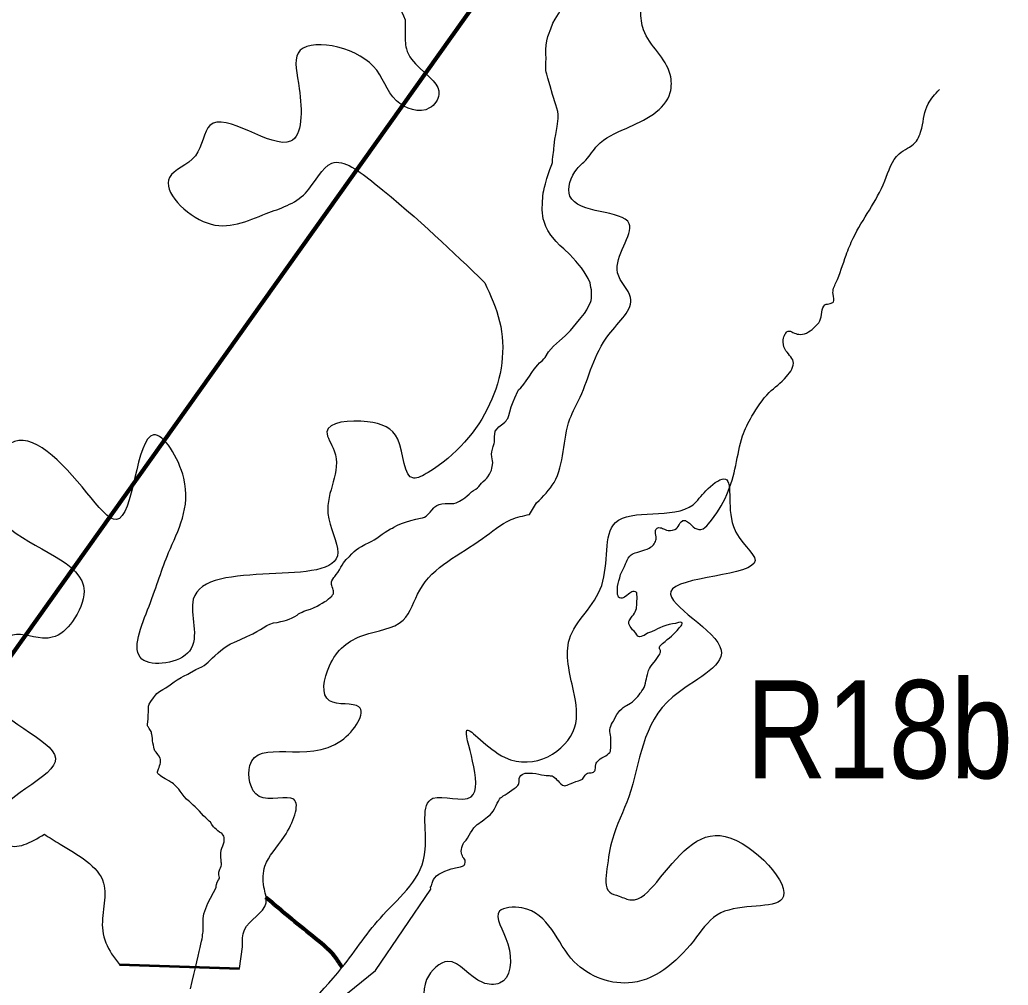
# Model space of a CAD drawing. Extents: x 553962 to 842807, y 8883888 to 9032388.
# Drawn here: x 709342 to 714375, y 8962615 to 8967533 of the extents above; entities that cross this region are included whole.
import ezdxf
from ezdxf.enums import TextEntityAlignment as Align

# ---------------------------------------------------------------- set-up
doc = ezdxf.new("R2010")
doc.units = 0
doc.header["$LTSCALE"] = 200
for name, color, linetype, lineweight in [('24', 7, 'Continuous', 25), ('50', 7, 'Continuous', 80), ('51', 7, 'Continuous', 25), ('9', 7, 'Continuous', 90)]:
    doc.layers.add(name, color=color, linetype=linetype, lineweight=lineweight)
doc.layers.add('53', color=7, linetype='Continuous')

msp = doc.modelspace()

# ---------------------------------------------------------------- linework, layer by layer
at = {"layer": '24'}
for points in [[(712046.7, 8967486.3), (712056.6, 8967515.1), (712068, 8967536.8), (712085.3, 8967563.8), (712094.3, 8967578.9), (712108.4, 8967604.9), (712114.9, 8967617.8), (712124.7, 8967632.2), (712136.2, 8967644.8), (712162, 8967671.2), (712191.7, 8967711.2)], [(712010.1, 8966662.7), (712013.6, 8966680.7), (712018.3, 8966697.9), (712026.1, 8966724.5), (712034.9, 8966749.9), (712041.8, 8966770), (712048.3, 8966786.7), (712051.1, 8966796), (712053.9, 8966805.4), (712055.1, 8966820.5), (712056.4, 8966835.5), (712060.8, 8966868), (712061.7, 8966875.3), (712063.1, 8966891.8), (712067.3, 8966924.5), (712071.5, 8966948.2), (712079.1, 8966989.8), (712083.9, 8967030.2), (712084.2, 8967050), (712082.3, 8967065.3), (712071.5, 8967099), (712054.8, 8967152.1), (712043.2, 8967196.6), (712031.2, 8967236.3), (712025.9, 8967255.3), (712022.9, 8967266.6), (712021.3, 8967275.1), (712020.1, 8967289.9), (712021.3, 8967318.5), (712021.8, 8967333), (712019.9, 8967363), (712020.8, 8967382), (712022.9, 8967404.1), (712025.7, 8967426.3), (712030.2, 8967447.9), (712034.5, 8967455.4), (712046.7, 8967486.3)], [(711759.8, 8965408.9), (711762.8, 8965437.7), (711772.3, 8965449.9), (711782, 8965460.1), (711801.8, 8965475.1), (711812, 8965483.4), (711818.1, 8965490.2), (711822.9, 8965496.2), (711826.4, 8965502.4), (711831.9, 8965516.8), (711836.6, 8965535), (711844.2, 8965561.3), (711853.7, 8965587.6), (711862.3, 8965606.9), (711878.9, 8965640.7), (711881.7, 8965647.3), (711893.7, 8965658.9), (711907.8, 8965676), (711921, 8965693.7), (711937.6, 8965716.8), (711948.9, 8965735.5), (711961.2, 8965752.8), (711979.2, 8965774.9), (711988.2, 8965784.6), (712003.5, 8965798), (712011.1, 8965805.6), (712017.1, 8965812.5), (712033.5, 8965840.7), (712059.2, 8965870.5), (712089.4, 8965897), (712119.3, 8965922.3), (712146.4, 8965950.7), (712192.1, 8966005.7), (712217.5, 8966036.2), (712228.7, 8966055.3), (712241.9, 8966080.2), (712247.9, 8966092.2), (712251.6, 8966102.6), (712253.4, 8966114.4), (712253.2, 8966120.2), (712253.4, 8966136.1), (712252.7, 8966157.1), (712250.2, 8966169.6), (712246, 8966192.4), (712235.8, 8966214.5), (712215.5, 8966249.6), (712202.1, 8966269.7), (712191.2, 8966283.1), (712173.9, 8966303.2), (712143.5, 8966337.1), (712111.7, 8966366.2), (712091.6, 8966383.7), (712072.8, 8966403.6), (712045.8, 8966436.3), (712030.5, 8966459.8), (712020.8, 8966479.7), (712012.2, 8966506.2), (712007.8, 8966519.2), (712005.3, 8966533.7), (712003.9, 8966547.6), (712002.7, 8966566.2), (712003.7, 8966600.8), (712005.5, 8966632), (712006.5, 8966651.9), (712010.1, 8966662.7)], [(711099.7, 8964859.2), (711120.7, 8964869.8), (711134.7, 8964876.2), (711147.4, 8964883.5), (711161, 8964892.7), (711174.5, 8964903), (711187.8, 8964912.1), (711202.9, 8964922.2), (711217, 8964931.3), (711230.3, 8964939.3), (711239.5, 8964943.7), (711247.4, 8964948.7), (711265.6, 8964957.7), (711286, 8964966.3), (711305.5, 8964973.4), (711334.1, 8964982.8), (711358.9, 8964988.4), (711381.9, 8964993.7), (711392.8, 8964996.2), (711403.7, 8965000), (711411.9, 8965003.8), (711419, 8965010.9), (711432, 8965024.8), (711439.7, 8965034.5), (711450.9, 8965046), (711456.2, 8965052.5), (711466, 8965058.7), (711477.8, 8965064.3), (711491.9, 8965066.9), (711508.5, 8965068.4), (711519.7, 8965068.4), (711532, 8965068.8), (711539, 8965068.8), (711545.8, 8965068.8), (711552.3, 8965069.7), (711564.4, 8965073), (711580.7, 8965080), (711598.1, 8965090.7), (711608.4, 8965097.7), (711619.6, 8965107.5), (711630.5, 8965116.6), (711636.6, 8965123.5), (711642.2, 8965128), (711652.5, 8965134.4), (711664.9, 8965142.4), (711673.5, 8965148.9), (711679.4, 8965154.8), (711686.5, 8965163.6), (711692.4, 8965171.9), (711702.1, 8965181.3), (711711.6, 8965189), (711715.2, 8965192.5), (711719.9, 8965197.2), (711725.5, 8965204.8), (711734.4, 8965219), (711739.7, 8965228.7), (711743.5, 8965239), (711746.5, 8965248.2), (711748.2, 8965257.3), (711748.8, 8965265), (711750.3, 8965277.4), (711749.5, 8965286.2), (711747.7, 8965295.9), (711745, 8965307.4), (711743.6, 8965319.8), (711745.3, 8965332.2), (711748.9, 8965344.8), (711753.3, 8965359.9), (711757.7, 8965374.3), (711758.6, 8965382), (711758.9, 8965390.2), (711759.8, 8965401.7), (711759.8, 8965408.9)], [(712421.5, 8964748.8), (712426.5, 8964761.1), (712431.3, 8964771.9), (712434.6, 8964780.6), (712440.2, 8964790.3), (712447.7, 8964800.3), (712455, 8964807.6), (712460, 8964811.5), (712466.4, 8964814.6), (712475.8, 8964817), (712489.2, 8964821.2), (712503.7, 8964825.6), (712514.6, 8964829.5), (712524.9, 8964832.9), (712536.6, 8964836.8), (712547.2, 8964841.8), (712554.2, 8964846), (712560.1, 8964850.4), (712564, 8964853.5), (712568.7, 8964858.5), (712572.9, 8964864.1), (712575.7, 8964869.4), (712578.2, 8964875.8), (712581, 8964882.2), (712582.1, 8964887.8), (712582.1, 8964894.2), (712581.8, 8964899.4), (712580.7, 8964907.5), (712579.6, 8964916.1), (712579, 8964925.6), (712579, 8964931.7), (712580.2, 8964935.9), (712583.5, 8964940.6), (712587.1, 8964943.4), (712590.5, 8964945.7), (712596.1, 8964946.2), (712603.6, 8964945.7), (712610, 8964944.3), (712614.8, 8964942.3), (712619.8, 8964939.8), (712624.8, 8964937.3), (712628.9, 8964935.6), (712634.8, 8964933.4), (712643.5, 8964931.5), (712654.6, 8964931.5), (712665.8, 8964933.1), (712678, 8964937), (712685.3, 8964940.7), (712689.2, 8964944.3), (712694.8, 8964952.1), (712700.1, 8964960.4), (712705.4, 8964969.6), (712709.6, 8964975.5), (712715.7, 8964980), (712719, 8964982.2), (712724.1, 8964983), (712728.5, 8964983), (712732.4, 8964981.6), (712735.5, 8964979.4), (712742.2, 8964975.2), (712751.4, 8964968.5), (712759.2, 8964961.6), (712771.2, 8964950.7), (712778.7, 8964943.7), (712788.8, 8964939.7)], [(710000.6, 8963922), (709997.1, 8963929.1), (709994.4, 8963933.2), (709992.9, 8963937.1), (709992.3, 8963944.1), (709993.5, 8963956.8), (709995.3, 8963972.7), (709995.9, 8963988.3), (709997, 8964009.5), (709997, 8964025.7), (709997.6, 8964037.2), (710000.6, 8964046.7), (710009.7, 8964060.8), (710023.7, 8964079.6), (710032.8, 8964091.9), (710040.8, 8964100.5), (710053.5, 8964110.8), (710070.6, 8964121.1), (710085.3, 8964130), (710108.5, 8964144.7), (710128.6, 8964161.2), (710143.6, 8964170.3), (710163.7, 8964183.3), (710175.5, 8964189.5), (710198.5, 8964199.8), (710207.1, 8964204.8), (710239.1, 8964222.6), (710269, 8964236.8), (710280.8, 8964244.5), (710300.8, 8964260.7), (710318.8, 8964277.8), (710324.1, 8964282.8), (710334.9, 8964292.4), (710352.3, 8964308), (710365.6, 8964319.5), (710381.8, 8964332.8), (710398.6, 8964344), (710415.8, 8964353.7), (710432, 8964361.1), (710465.5, 8964376), (710498.9, 8964391), (710528.1, 8964404.3), (710549.6, 8964416.4), (710567.2, 8964426.9), (710581.1, 8964436), (710600.6, 8964447), (710615.1, 8964454.3), (710633.7, 8964461.1), (710652, 8964463.5), (710671.7, 8964467.6), (710688.3, 8964470.8), (710699.5, 8964474.7), (710713.8, 8964479.8), (710728.9, 8964486.9), (710742.8, 8964493.1), (710755.2, 8964500.7), (710762.2, 8964506.3), (710768.7, 8964511), (710780, 8964516), (710789.1, 8964519.9), (710804.5, 8964525.5), (710822.7, 8964530.8), (710837.2, 8964537.9), (710856, 8964546), (710870.1, 8964554), (710881.6, 8964561.9), (710894.9, 8964569.9), (710903.8, 8964573.7), (710914.7, 8964583.2), (710923, 8964589.9), (710931.2, 8964597.6), (710935.3, 8964602.9), (710939.2, 8964609.1), (710940.1, 8964615.3), (710940.2, 8964623.8), (710938.7, 8964629.9), (710936.9, 8964636.7), (710933.1, 8964645), (710930.7, 8964651.2), (710929.2, 8964656.8), (710928.9, 8964662.4), (710929.8, 8964669.2), (710931.9, 8964675.1), (710935.4, 8964682.7), (710941.9, 8964691.8), (710946.3, 8964697.5), (710953.8, 8964707.1), (710960.9, 8964717.7), (710970, 8964730.7), (710977.7, 8964744), (710983.9, 8964754.9), (710990.4, 8964766.4), (710997.2, 8964774.6), (711004.6, 8964783.2), (711020.6, 8964799.3), (711033.6, 8964812.3), (711045.1, 8964823.8), (711055.7, 8964832.3), (711067.5, 8964840.6), (711082.3, 8964849.4), (711099.7, 8964859.2)], [(712479.6, 8964525.8), (712481.6, 8964533.3), (712482.7, 8964541.1), (712483.2, 8964550.3), (712483.8, 8964560.5), (712484.4, 8964573.6), (712485, 8964582.2), (712485, 8964591.4), (712483.8, 8964606.2), (712483.8, 8964613.4), (712481.3, 8964617.1), (712476.6, 8964619.3), (712470.7, 8964620.7), (712463.8, 8964620.1), (712458.8, 8964618.2), (712448.8, 8964612.1), (712441, 8964607), (712432.3, 8964600.3), (712421.7, 8964591.7), (712415, 8964587.8), (712409.2, 8964587.2), (712402.8, 8964586.4), (712395.8, 8964588.6), (712390.5, 8964592.3), (712388.2, 8964598.1), (712386, 8964605.4), (712385.2, 8964611.2), (712385.5, 8964621.5), (712384.9, 8964634), (712386.1, 8964646), (712388.3, 8964661.9), (712392.7, 8964675.6), (712396.7, 8964690.6), (712401.4, 8964706.8), (712407.8, 8964721.5), (712415.9, 8964737.1), (712421.5, 8964748.8)], [(712600.3, 8964302.1), (712603.4, 8964308), (712604.8, 8964311.1), (712605.3, 8964314.4), (712604.8, 8964319.7), (712603.1, 8964323), (712600.9, 8964325.8), (712599.2, 8964330.3), (712598.7, 8964334.2), (712599.8, 8964337.5), (712601.4, 8964341.7), (712604.8, 8964346.2), (712609.8, 8964350.6), (712615.1, 8964355.3), (712628.8, 8964366.5), (712638.3, 8964375.4), (712650.5, 8964385.2), (712660.2, 8964393.8), (712668.8, 8964401), (712677.8, 8964410), (712689.8, 8964422.2), (712696.5, 8964430.3), (712701.5, 8964436.7), (712709.8, 8964445.6), (712713.5, 8964450.3), (712715.4, 8964457), (712715.4, 8964460.9), (712711.8, 8964463.2), (712705.1, 8964464), (712695.6, 8964462.3), (712680.3, 8964458.4), (712665.5, 8964456.2), (712648, 8964452.2), (712631.8, 8964446.9), (712615.9, 8964442.5), (712600.6, 8964435.8), (712589.1, 8964429.9), (712577.4, 8964424.3), (712558.7, 8964416), (712538.9, 8964407.9), (712520.6, 8964397.3), (712515, 8964394), (712505.5, 8964390.7), (712498, 8964389.8), (712492.4, 8964391.2), (712489.6, 8964393.4), (712484, 8964400.1), (712478.7, 8964408.2), (712470.1, 8964417.7), (712462, 8964426), (712455.8, 8964435.5), (712450.5, 8964442.2), (712446.1, 8964449.4), (712443.3, 8964455.6), (712443.3, 8964460.6), (712443.3, 8964465.3), (712443.9, 8964467.8), (712445.3, 8964471.7), (712448.9, 8964477), (712453.4, 8964484), (712460.3, 8964494.3), (712466.2, 8964501), (712472.6, 8964510.7), (712476.2, 8964517.7), (712479.6, 8964525.8)], [(712364.7, 8963959.7), (712369, 8963967.4), (712374, 8963979.4), (712382.1, 8963994.2), (712391.6, 8964008.1), (712397.2, 8964015.1), (712407.2, 8964023.7), (712414.7, 8964029.3), (712425.1, 8964036.3), (712431.6, 8964040.4), (712451.1, 8964051.2), (712462, 8964058.8), (712470.7, 8964066.8), (712480.2, 8964076.6), (712488.5, 8964085), (712495.5, 8964093.9), (712501.6, 8964102.5), (712505.9, 8964108.6), (712510.1, 8964115), (712516.8, 8964123.3), (712521.6, 8964132.2), (712524.6, 8964141.4), (712527.7, 8964153.4), (712529.9, 8964164.8), (712532.7, 8964175.4), (712535.5, 8964185.8), (712537.5, 8964198.3), (712541.4, 8964211.4), (712543.9, 8964218.9), (712548.1, 8964228.1), (712554.2, 8964237), (712562.9, 8964248.1), (712571.5, 8964260.7), (712579.4, 8964269), (712590, 8964284.1), (712596.7, 8964295.4), (712600.3, 8964302.1)], [(712058, 8963677.9), (712064.5, 8963673.2), (712070.9, 8963667.3), (712075.7, 8963662.8), (712082.7, 8963655.8), (712088.8, 8963649.4), (712097.8, 8963640.5), (712105.9, 8963634.6), (712111.7, 8963631.8), (712117.6, 8963631.5), (712122.6, 8963632.4), (712129.6, 8963634.1), (712136, 8963636.8), (712144.1, 8963640.2), (712158.2, 8963646.8), (712172.7, 8963652.3), (712186.9, 8963656.2), (712195.8, 8963659.8), (712206.7, 8963664.9), (712211.5, 8963669.6), (712214.5, 8963674.6), (712220.7, 8963684.6), (712224.3, 8963689.1), (712227.7, 8963692.2), (712232.4, 8963695.2), (712239.1, 8963696.6), (712244.4, 8963697.5), (712251.4, 8963697.7), (712258.6, 8963698.3), (712263.1, 8963700), (712266.7, 8963703.3), (712269.8, 8963706.4), (712271.2, 8963710.3), (712272, 8963714.7), (712272.9, 8963720.2), (712273.7, 8963729.4), (712275.1, 8963740.3), (712277.1, 8963746.2), (712279.9, 8963750.6), (712282.9, 8963754.2), (712290.2, 8963761.2), (712297.4, 8963767.6), (712305.2, 8963772.9), (712316.1, 8963778.5), (712326.2, 8963784.3), (712333.8, 8963789.8), (712340.5, 8963795.4), (712346.3, 8963800.7), (712349.4, 8963807.4), (712350.5, 8963814.6), (712351.3, 8963823), (712351.6, 8963830.8), (712351.9, 8963841.9), (712351.9, 8963855.3), (712351.9, 8963871.4), (712352.2, 8963880.8), (712350.5, 8963887.5), (712348, 8963898.4), (712346.6, 8963905.9), (712346.6, 8963916), (712348, 8963926.3), (712351.1, 8963935.2), (712355.8, 8963944.4), (712360.8, 8963953.3), (712364.7, 8963959.7)], [(710341.7, 8963112), (710341.4, 8963118.8), (710343.5, 8963128.8), (710347.6, 8963139.4), (710354.1, 8963151.2), (710357.1, 8963156.2), (710358.5, 8963160.6), (710358.8, 8963163.6), (710357.9, 8963170.6), (710356.5, 8963178), (710355.6, 8963184.5), (710356.2, 8963190.1), (710358, 8963196.8), (710361.5, 8963206.8), (710364.5, 8963213.6), (710368.3, 8963221.3), (710369.5, 8963228.1), (710368.6, 8963236.9), (710367.1, 8963241.9), (710366.8, 8963249.6), (710365.6, 8963268.8), (710365.6, 8963287.6), (710367.7, 8963303.5), (710370.7, 8963313.2), (710376.6, 8963324.4), (710380.1, 8963334.5), (710382.8, 8963345.1), (710383.7, 8963357.7), (710383.1, 8963367.8), (710381.6, 8963373.7), (710378.1, 8963379.6), (710373, 8963385.8), (710370.3, 8963388.6), (710365.3, 8963391.5), (710358.8, 8963395.4), (710350.6, 8963401.6), (710343.8, 8963407.5), (710335.8, 8963415.4), (710329.3, 8963421.3), (710320.2, 8963434), (710312.5, 8963445.2), (710306.3, 8963450.8), (710298, 8963459.9), (710289.9, 8963467.5), (710278.4, 8963477.9), (710266.9, 8963490.5), (710256.9, 8963502.3), (710245.7, 8963513.2), (710235.6, 8963523), (710225.9, 8963531.8), (710215.8, 8963541), (710206.1, 8963550.1), (710201.1, 8963553.9), (710191.5, 8963563.6), (710180, 8963576.6), (710168.8, 8963590.4), (710158.4, 8963602.8), (710151.4, 8963613.1), (710145.5, 8963621.1), (710133.7, 8963633.2), (710125.7, 8963640.2), (710118, 8963645.8), (710112, 8963649.9), (710101.7, 8963656.4), (710090.1, 8963662.2), (710082.8, 8963666.7), (710073.6, 8963671.1), (710065.1, 8963676.4), (710058.6, 8963681.4), (710055, 8963685), (710050, 8963688.5), (710045.3, 8963693.2), (710043.8, 8963697), (710043.2, 8963702.1), (710045, 8963707.7), (710049.1, 8963718), (710052.1, 8963724.8), (710054.4, 8963732.6), (710057.4, 8963740.3), (710059.2, 8963748), (710059.2, 8963757.1), (710058.6, 8963764.2), (710056.2, 8963771.8), (710050.3, 8963783.3), (710045, 8963790.7), (710036.4, 8963801.9), (710030.5, 8963808.3), (710027.8, 8963813.7), (710025.7, 8963818.7), (710024.6, 8963828.1), (710023.1, 8963838.4), (710020.4, 8963850.5), (710018.7, 8963860.5), (710017.8, 8963872.3), (710015.7, 8963882.9), (710013.9, 8963891.5), (710012.2, 8963898), (710012.1, 8963902.3), (710011.2, 8963906.7), (710007.7, 8963913.2), (710000.6, 8963922)], [(711773.5, 8963542.3), (711780.2, 8963553.4), (711784.1, 8963562.6), (711789.9, 8963568.8), (711796.1, 8963573.8), (711804.2, 8963579.6), (711812.8, 8963585.5), (711824, 8963592.2), (711835.1, 8963599.4), (711846.8, 8963608.1), (711858.8, 8963616.4), (711869.4, 8963624.5), (711877.5, 8963631.7), (711880.7, 8963636.7), (711883.2, 8963642.3), (711884.6, 8963651.2), (711885.4, 8963658.7), (711885.7, 8963667.4), (711887.9, 8963675.7), (711892.9, 8963684.1), (711900.2, 8963688.6), (711906.6, 8963692.2), (711915.5, 8963694.4), (711925, 8963695), (711931.7, 8963695.2), (711952.6, 8963694.9), (711970.4, 8963693), (711985.2, 8963690.5), (711997.8, 8963687.1), (712012, 8963684.9), (712022.3, 8963683.2), (712027.3, 8963683), (712036.8, 8963682.7), (712042.7, 8963682.1), (712049.4, 8963682.1), (712053.3, 8963681), (712058, 8963677.9)], [(711435.9, 8963104.2), (711433.8, 8963114), (711437.7, 8963122.1), (711442.2, 8963135.5), (711445.2, 8963144.7), (711449.4, 8963153.9), (711455, 8963162.8), (711463.9, 8963172), (711476.2, 8963180.1), (711489.3, 8963188.1), (711506.3, 8963195.7), (711525, 8963202.6), (711538.8, 8963207.9), (711547.8, 8963210.4), (711560.6, 8963213.7), (711586.8, 8963217.9), (711596.9, 8963220.7), (711603, 8963224.1), (711606.4, 8963228.5), (711608.3, 8963233.8), (711609.7, 8963240.8), (711610.3, 8963246.9), (711609.4, 8963251.6), (711606.9, 8963256.4), (711602.7, 8963261.7), (711598.6, 8963267), (711595.8, 8963273.7), (711592.7, 8963281.1), (711590.5, 8963288.3), (711589.9, 8963297.2), (711591.3, 8963307), (711593, 8963316.8), (711596.3, 8963326.2), (711600.5, 8963335.1), (711603.6, 8963342.4), (711607.8, 8963346.6), (711614.7, 8963353.3), (711618.1, 8963358.8), (711622, 8963364.9), (711630.1, 8963379.4), (711637.1, 8963391.1), (711645.7, 8963403.6), (711654.7, 8963415.9), (711663, 8963425.6), (711671.7, 8963433.4), (711679.2, 8963439.3), (711687.3, 8963444.9), (711695.8, 8963451.5), (711707, 8963459.3), (711723.4, 8963472.1), (711737.1, 8963483.5), (711745.2, 8963492.7), (711751.9, 8963501.6), (711758.6, 8963513.6), (711763.3, 8963521.1), (711768.1, 8963530.1), (711773.5, 8963542.3)], [(710211.7, 8962596.3), (710220, 8962633.4), (710228.3, 8962669.3), (710236.4, 8962703.3), (710243.8, 8962734.7), (710250.5, 8962762.6), (710256.1, 8962786.7), (710260.8, 8962807), (710264.6, 8962824.2), (710267.7, 8962838.7), (710270.1, 8962851), (710271.9, 8962861.6), (710273.3, 8962870.9), (710274.4, 8962879.4), (710275.3, 8962887.5), (710275.9, 8962895.5), (710276.3, 8962903.4), (710276.6, 8962911.3), (710276.6, 8962919.3), (710276.5, 8962927.5), (710276.2, 8962936), (710275.8, 8962945), (710275.2, 8962954.4), (710280.1, 8962978.4), (710299.5, 8963033.2), (710341.7, 8963112)], [(710674.9, 8962204.1), (710737.2, 8962184.8), (710790.9, 8962198.1), (710985, 8962463.8), (711011.2, 8962574.6), (711153.5, 8962689.4), (711435.9, 8963104.2)]]:
    msp.add_lwpolyline(points, dxfattribs=at)
for points in [[(712788.8, 8964939.7), (712810, 8964936.4), (712849.2, 8964965.8), (712942.3, 8965114.4), (712988, 8965263.1), (713022.3, 8965413.3), (713069.7, 8965512.9), (713157.9, 8965633.8), (713246.1, 8965715.4), (713280.3, 8965792.2), (713237.9, 8965855.9), (713229.7, 8965902.9), (713239.5, 8965932.3), (713254.2, 8965947.1), (713278.7, 8965940.5), (713308.1, 8965930.7), (713347.3, 8965937.3), (713384.8, 8965963.4), (713415.9, 8965999.3), (713425.7, 8966043.5), (713442, 8966081), (713468.1, 8966087.6), (713484.5, 8966095.8), (713482.8, 8966135), (713497.5, 8966192.2), (713549.8, 8966334.3), (713585.7, 8966420.9), (713746.6, 8966711.8), (713820.1, 8966850.6), (713901.8, 8966907.8), (713934.4, 8966981.3), (713967.1, 8967103.9), (714024.2, 8967177.4)], [(710131.8, 8961656.3), (710038.2, 8961644.6), (709952.5, 8961734.3), (709819.9, 8961831.8), (709687.4, 8961917.5), (709656.2, 8962018.9), (709609.4, 8962151.4), (709543.1, 8962295.7), (709476.8, 8962369.8), (709379.4, 8962377.6), (709293.6, 8962323), (709126, 8962209.9), (708970, 8962096.9), (708782.9, 8962007.2), (708568.5, 8961929.2), (708381.3, 8961917.5), (708221.5, 8961987.7), (708096.8, 8962093), (707991.5, 8962217.7), (707749.8, 8962326.9), (707512, 8962326.9), (707301.5, 8962284), (707215.7, 8962330.8), (707145.5, 8962459.4), (707075.3, 8962576.4), (706915.5, 8962654.3), (706724.5, 8962763.5), (706475, 8962868.8), (706285.5, 8962993.6), (706252.3, 8963024.5), (706110.5, 8963180), (706048.8, 8963234.9), (705965.3, 8963310.3), (705863.5, 8963374.4), (705840.7, 8963390.4), (705796.9, 8963407.8)]]:
    msp.add_spline(points, degree=3, dxfattribs=at)
at = {"layer": '50'}
msp.add_spline([(710593.7, 8963064.2), (710832, 8962866.8), (710942.5, 8962765.3), (710982.7, 8962704.5)], degree=3, dxfattribs=at)
at = {"layer": '51'}
msp.add_line((711937.1, 8965013.4), (711973.9, 8965072.3), dxfattribs=at)
at = {"layer": '51', "lineweight": 53}
msp.add_line((709850.2, 8962719.8), (710461.6, 8962699.4), dxfattribs=at)
at = {"layer": '51'}
msp.add_lwpolyline([(709850.2, 8962719.8), (710461.6, 8962699.4), (710476.3, 8962811)], dxfattribs=at)
for points in [[(711973.9, 8965072.3), (712062.3, 8965175.5), (712143.3, 8965499.6), (712194.8, 8965610.2), (712341.9, 8965929.9), (712452.5, 8966118.5), (712386.2, 8966244.4), (712445.1, 8966494.2), (712143.3, 8966634.2), (712180.1, 8966774.2), (712224.2, 8966818.4), (712283.2, 8966892), (712429.2, 8966979.7), (712654.2, 8967162.3), (712654, 8967253.6), (712518.7, 8967481.4), (712504, 8967577.2), (712533.5, 8967761.4), (712592, 8967912.9), (712761.7, 8968070.8), (712960.5, 8968181.3), (712710.2, 8968763.3), (712770.2, 8968749.7), (712900.6, 8968704), (713387.5, 8968910.6)], [(712080.2, 8968171.6), (711826.7, 8968107.6), (711495.4, 8968498.1), (711208.2, 8968387.6), (711088.3, 8968070.2), (711018.6, 8967902.8), (711093.9, 8967862.2), (711237.7, 8967687.7), (711304, 8967533)], [(711304, 8967533), (711304, 8967466.7), (711310.7, 8967385.5), (711381.1, 8967284.1), (711476.7, 8967152.2), (711429.1, 8967083.6), (711259.8, 8967120.4), (711142, 8967297.2), (710759.2, 8967363.5), (710765, 8967182.7), (710720.6, 8966913.9), (710310.1, 8966995.2), (710236.4, 8966840.5), (710103.9, 8966730), (710295.8, 8966498), (710597.2, 8966545.8), (710796.5, 8966650.2), (710931.4, 8966802.3), (711147.2, 8966700.8), (711709.8, 8966193.7)], [(711709.8, 8966193.7), (711785.5, 8965995.9), (711421.8, 8965227.1), (711348.1, 8965197.6), (711267.2, 8965396.5), (711112.5, 8965484.9), (710906.4, 8965433.3), (710943.2, 8965337.6), (710911.2, 8965017.1), (710961.9, 8964819.3), (710225.9, 8964581), (710206.6, 8964317.3), (709964, 8964276.7), (710000.5, 8964545.5), (710100, 8964819.3), (710177.5, 8965197.6), (710022.9, 8965418.6), (709834, 8964986.7), (709684.3, 8965123.9), (709294.1, 8965374.4), (709183.6, 8965116.5), (709267.8, 8964961.4), (709669.6, 8964621.6), (709610.7, 8964468.2), (709507.6, 8964387.2), (709479.8, 8964383.2), (709304.4, 8964398.5), (709204.4, 8964317.3), (709185, 8964089.1), (709522.3, 8963753.6), (709216.9, 8963404.4), (709272, 8963333.7), (709467.5, 8963384.1)], [(710593, 8962308.9), (710982.7, 8962704.5), (711192.5, 8962973.3), (711407, 8963308), (711446, 8963567.2), (711639.8, 8963574.1), (711619, 8963913.5), (711812.8, 8963775), (712167, 8963926.7), (712161.5, 8964114.3), (712140.7, 8964378), (712305.3, 8964651.9), (712375.3, 8964972.2), (712770.2, 8965062.7), (712835.2, 8965133.7), (712927, 8965194.6), (712975.5, 8964952.2), (713086.2, 8964779.1), (712657.1, 8964619.8), (712913.2, 8964322), (712667.7, 8964083.9), (712442.6, 8963574.1), (712359.5, 8963359.5), (712331.9, 8963207.1), (712345.7, 8963089.4), (712394.1, 8963068.6), (712455.1, 8963049.3), (712585.1, 8963140.6), (712934, 8963373.3), (713224.6, 8963054.8), (712911.2, 8962983.3), (712788.6, 8962860.8), (712461.2, 8962628.3), (712165.3, 8962734.9), (711898.9, 8963008.7), (711785.1, 8962992.4), (711826.7, 8962826.2), (711785.1, 8962625.4), (711699.5, 8962628.4), (711522.1, 8962736.2), (711413.9, 8962643.6), (711425.2, 8962293), (711109.4, 8962187.2), (711004.6, 8962055.3), (710929.9, 8961867.7), (710890, 8961791.6)], [(710476.3, 8962811), (710486.1, 8962897.2), (710596, 8963034.2), (710585.7, 8963115.3), (710590.5, 8963221.8), (710690.3, 8963373.9), (710737.1, 8963562.1), (710560.4, 8963576.8), (710513.9, 8963734), (710979.6, 8963860.8), (711069.3, 8964033.2), (710918.9, 8964063.7), (710918.4, 8964241.2), (711093.3, 8964398.4), (711293.6, 8964474.4), (711378.3, 8964626.6), (711698.3, 8964890.3), (711843.4, 8964986.6), (711937.1, 8965013.4)], [(709467.5, 8963384.1), (709547.8, 8963333.4), (709768.9, 8963135.6), (709764.5, 8962892.2), (709810, 8962775.5), (709850.2, 8962719.8)]]:
    msp.add_spline(points, degree=3, dxfattribs=at)
at = {"layer": '9'}
msp.add_lwpolyline([(691582, 8951218.7), (697371.2, 8956056), (705081.2, 8958366.8), (713138.6, 8969695)], dxfattribs=at)

# ---------------------------------------------------------------- texts
at = {"layer": '53', "width": 0.85}
msp.add_text('R18b', height=500, dxfattribs=at).set_placement((713719.5, 8963668.9), align=Align.CENTER)

doc.saveas('drawing.dxf')
